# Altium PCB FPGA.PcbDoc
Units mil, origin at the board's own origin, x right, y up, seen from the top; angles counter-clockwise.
Board outline 6500 x 4500 mil, 6 copper layers (Top, VCC, GND, Route2, Route3, Bottom), stack 48.346 mil thick; 66 components, 103 nets, 452 pads, 0 vias.
Unrouted connection lines stored in the file: 258.
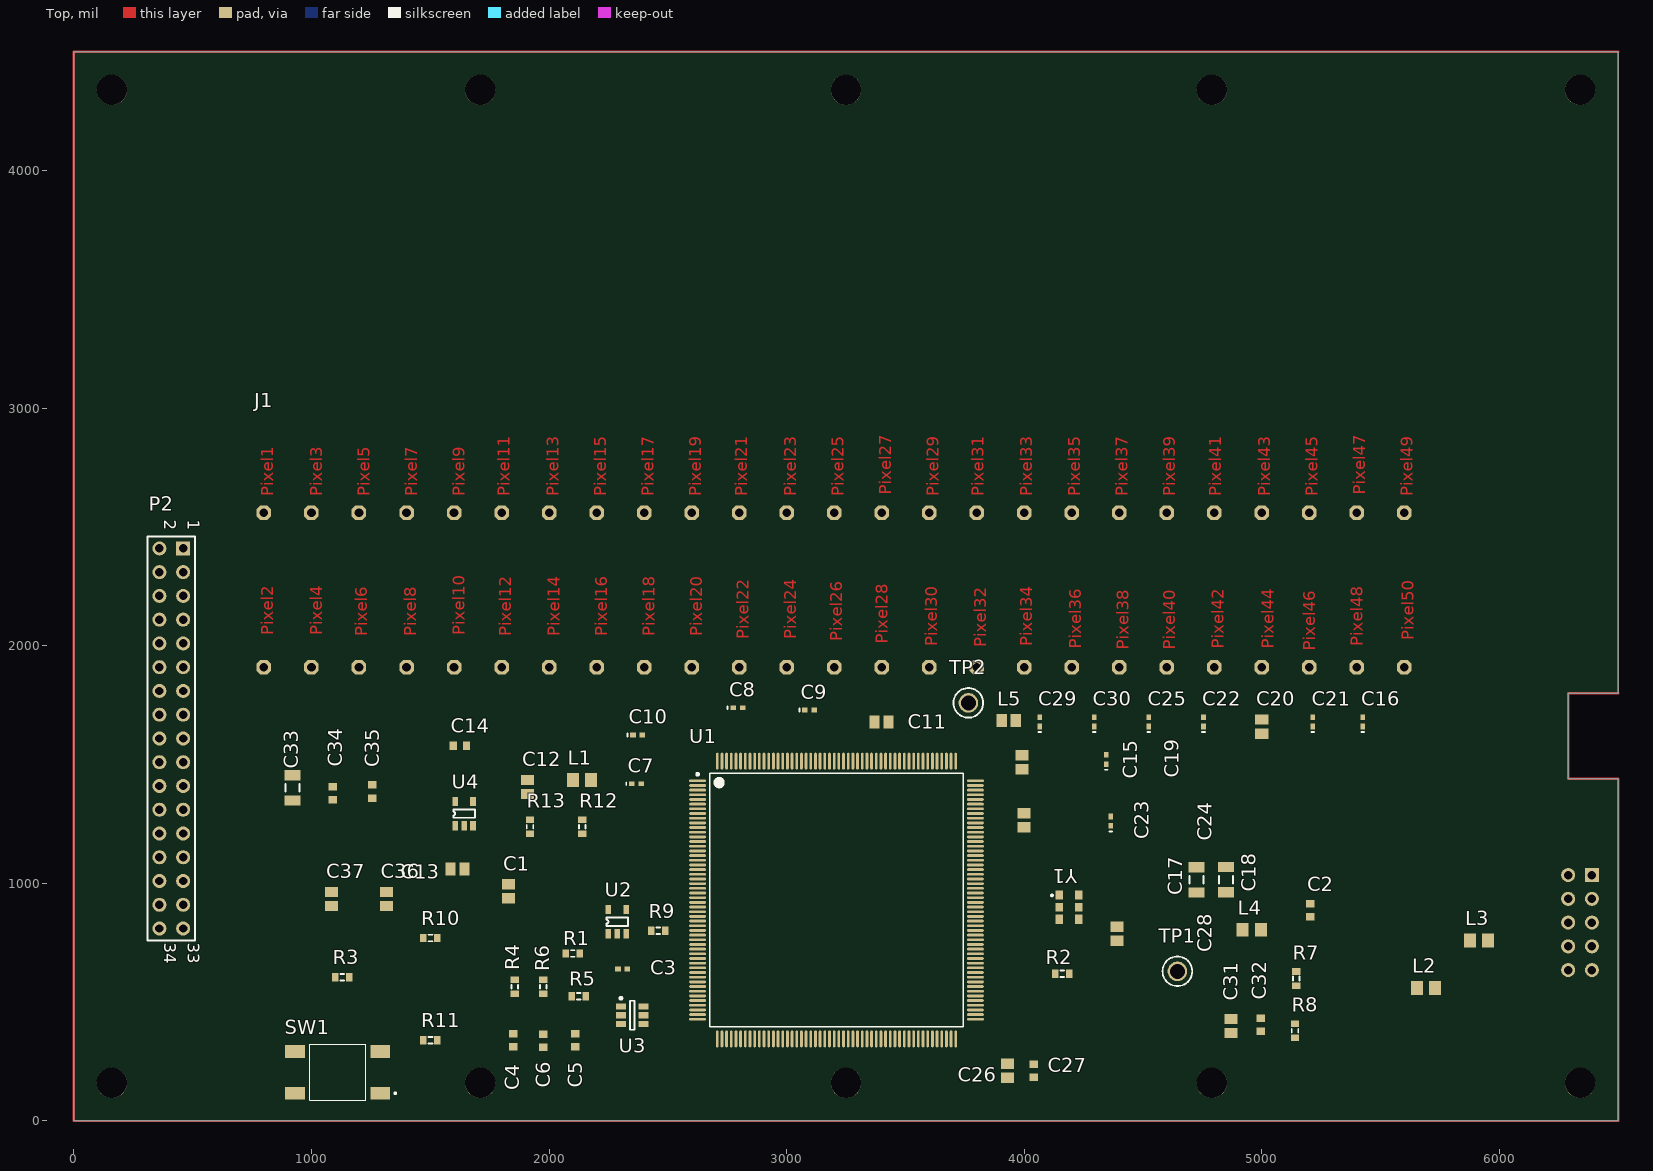
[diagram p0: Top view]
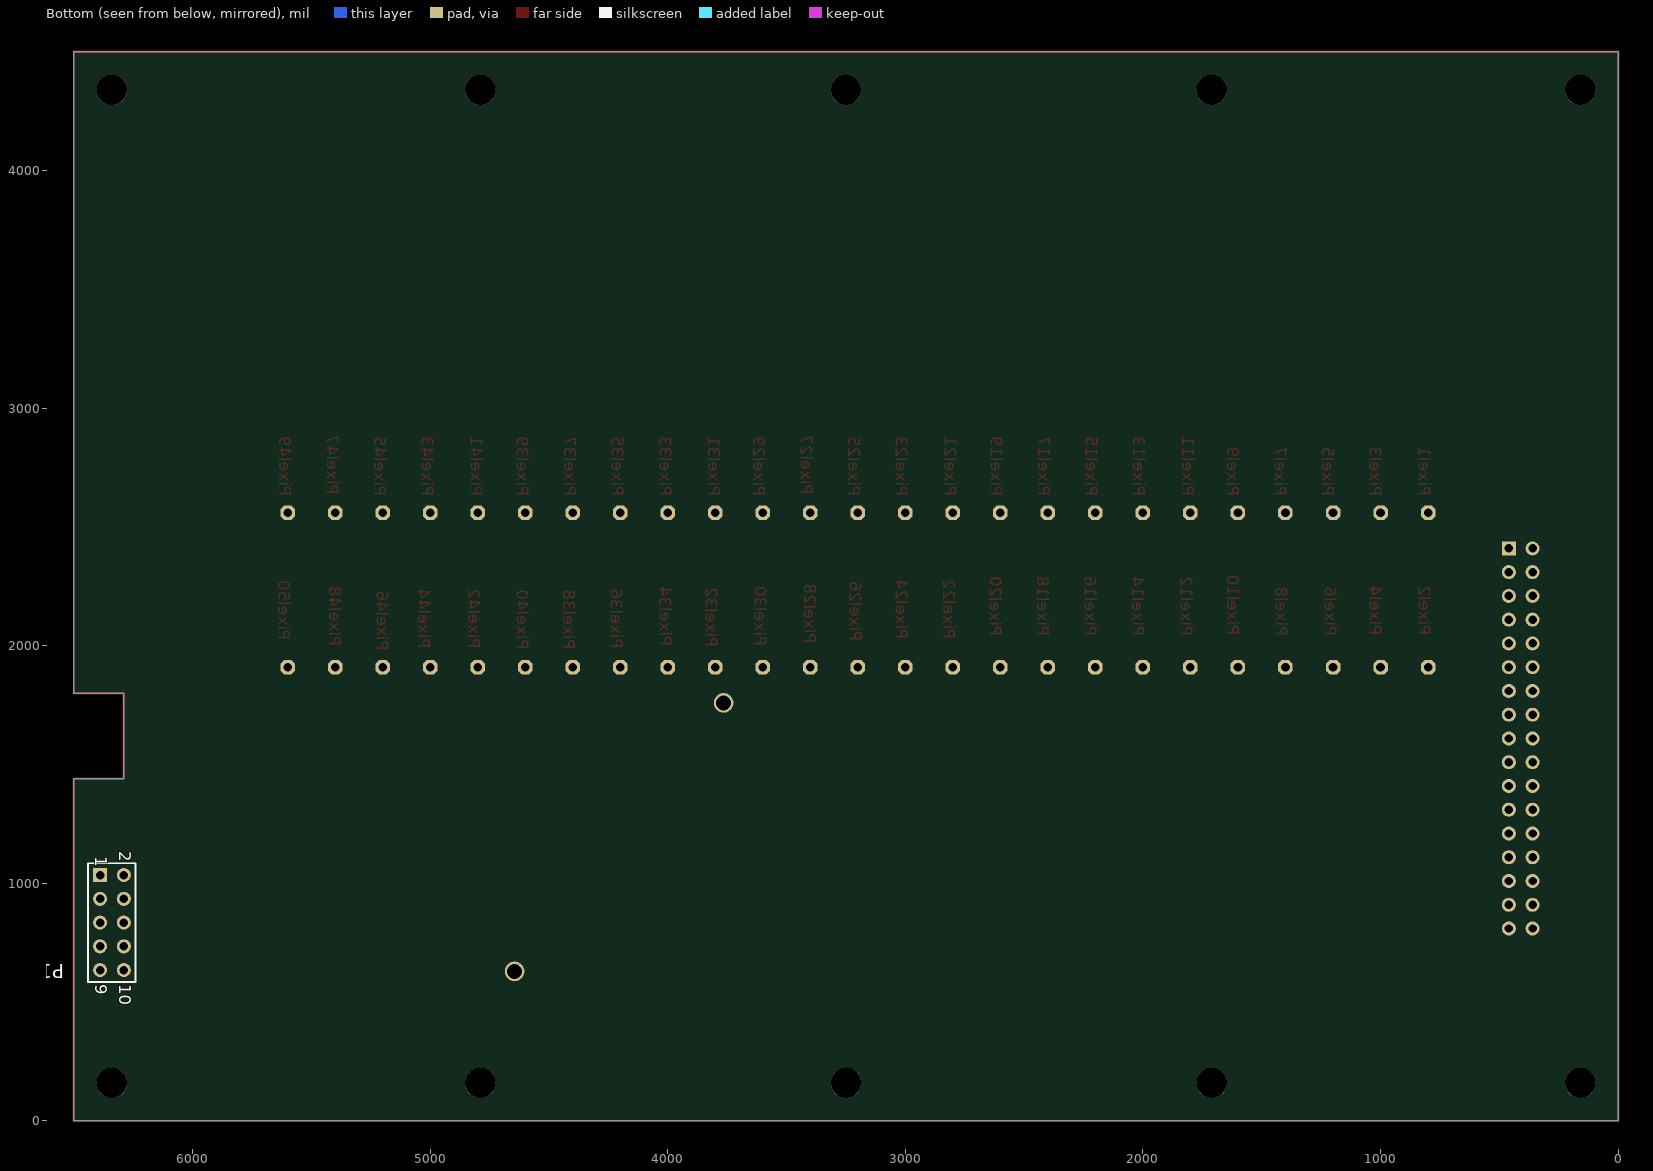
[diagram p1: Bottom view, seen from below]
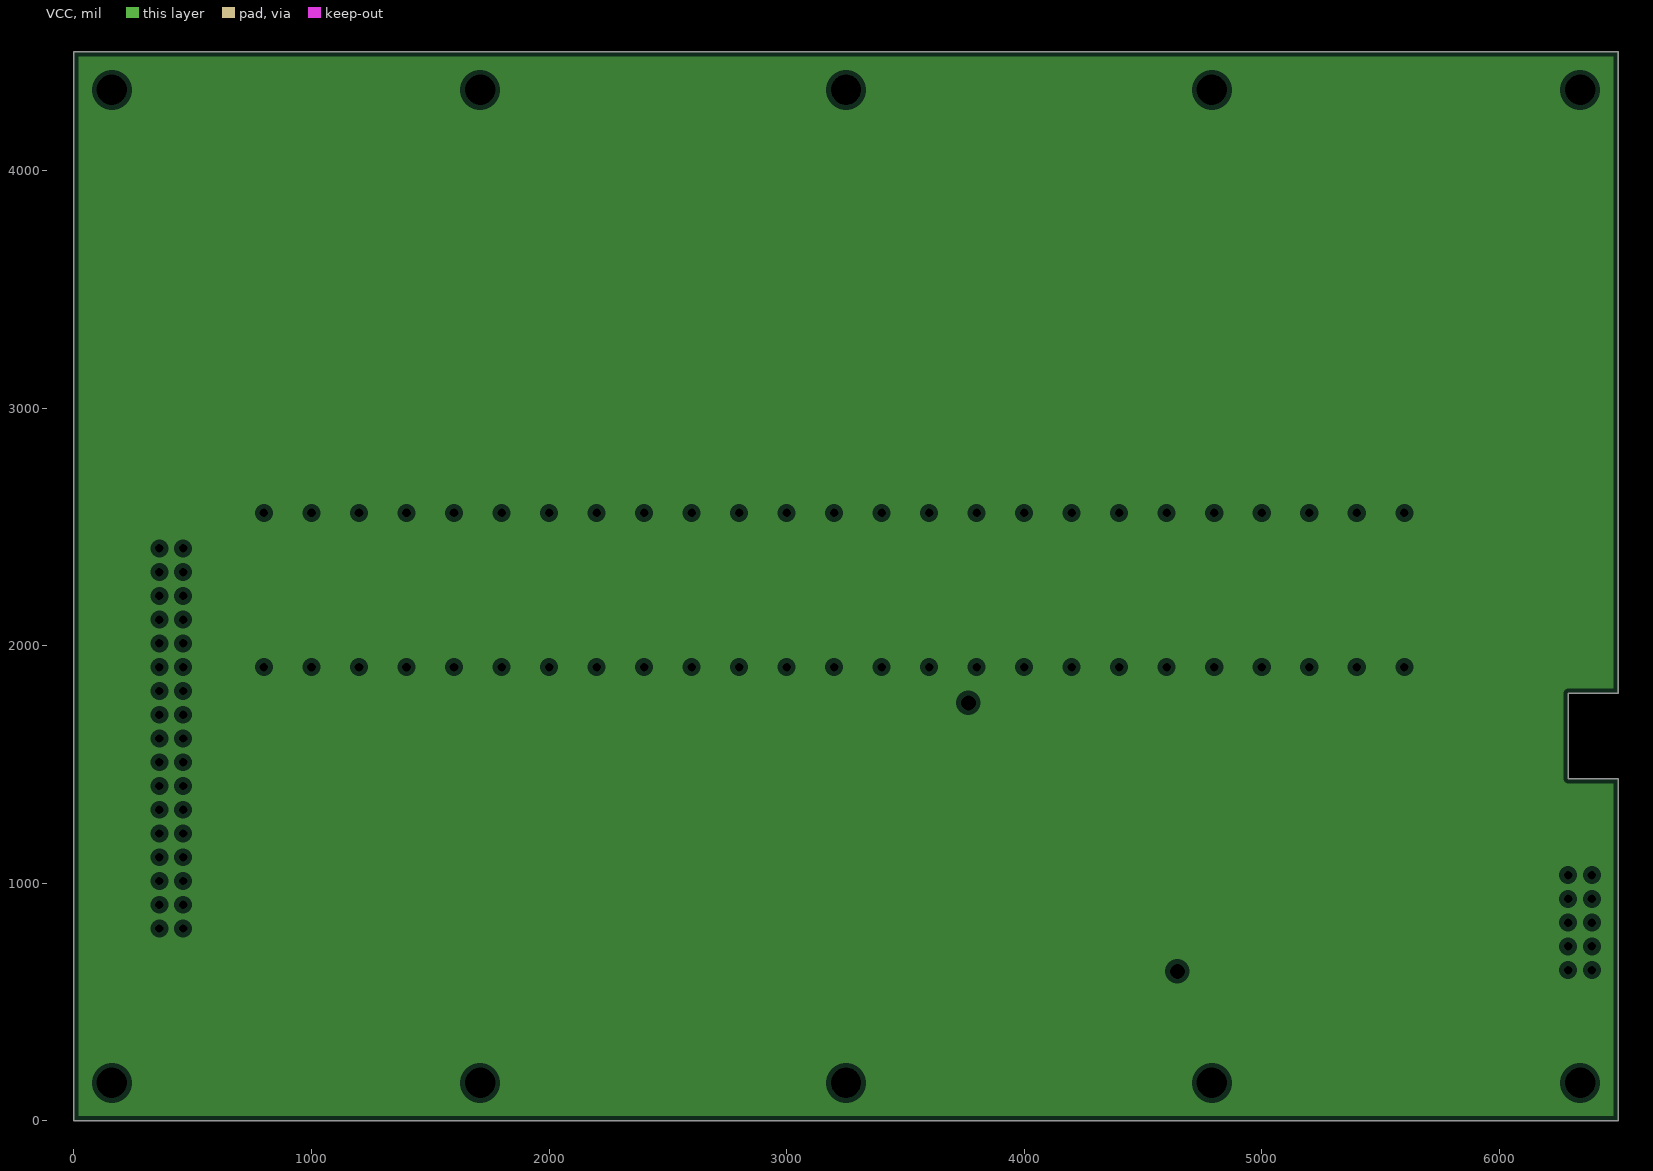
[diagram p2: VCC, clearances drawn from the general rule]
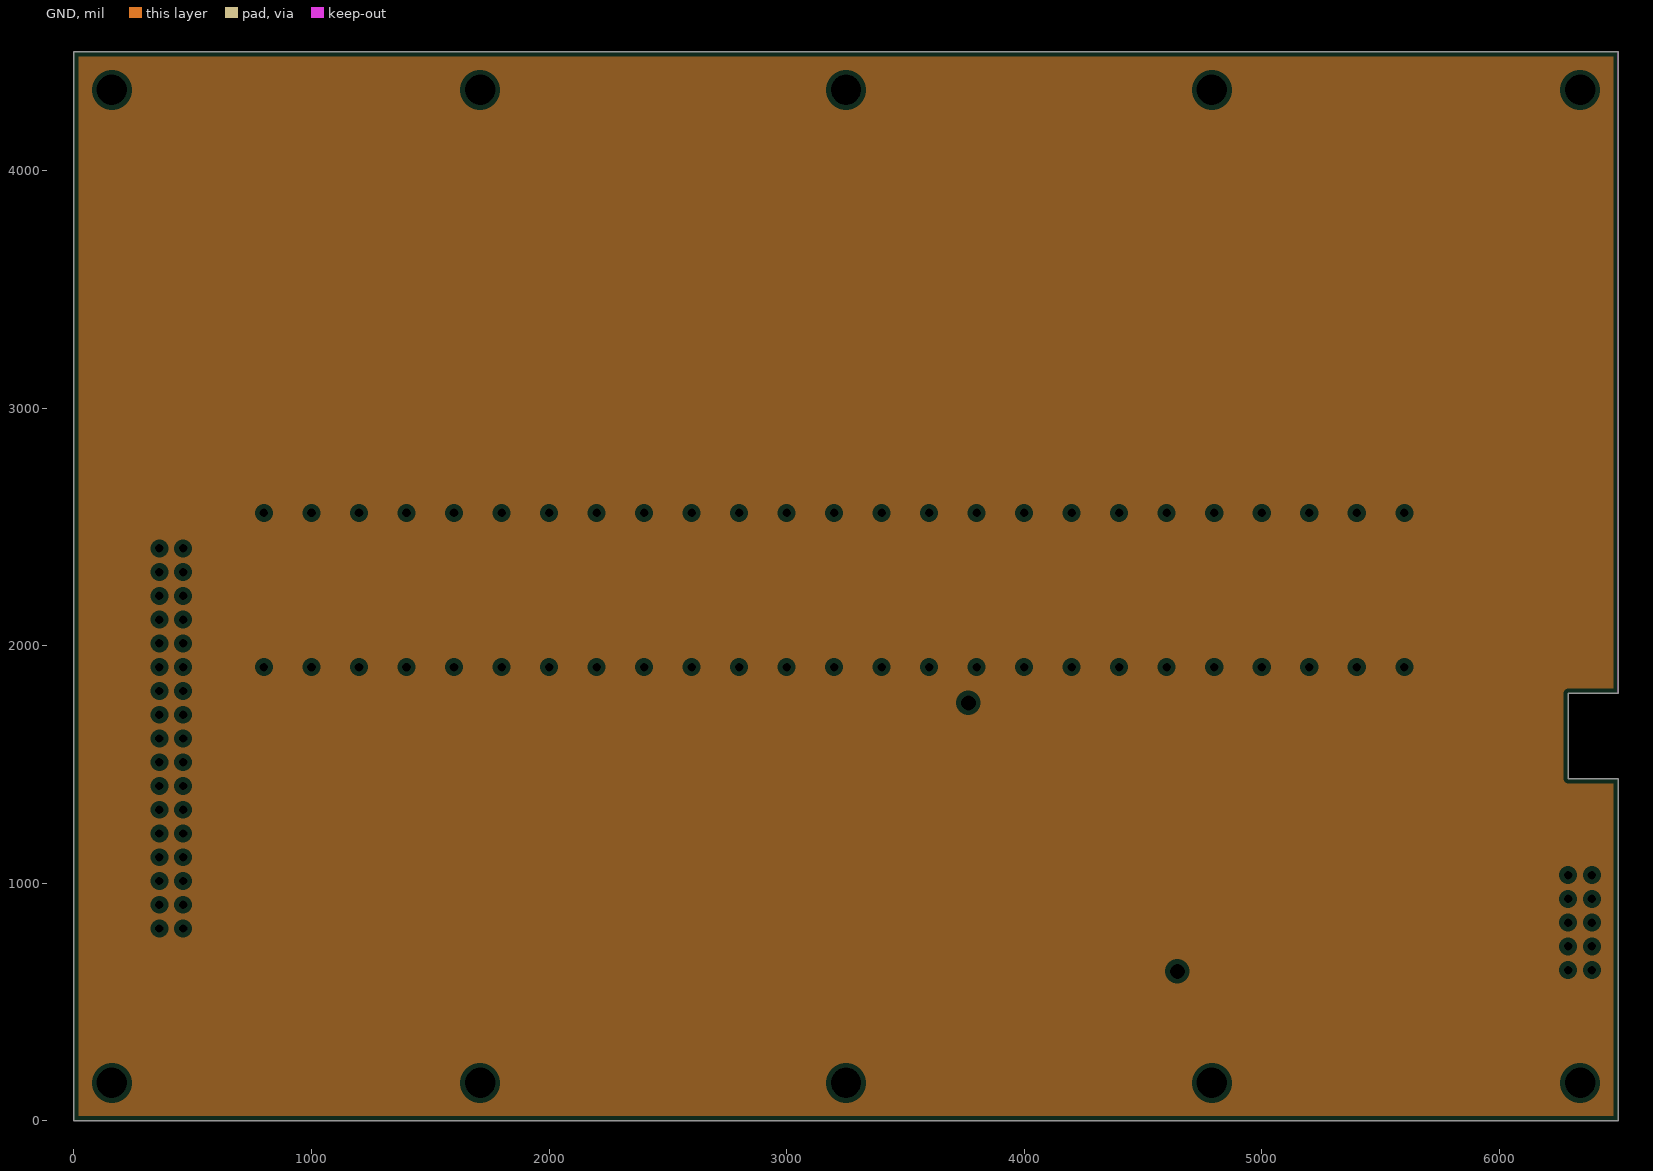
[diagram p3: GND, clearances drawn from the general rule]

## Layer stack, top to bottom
Top Solder: solder mask 0.4, Solder Resist, Dk 3.5
Top: signal copper 1.378
Dielectric 1: core 10, FR-4, Dk 4.2
VCC: plane copper 1.417
Dielectric 5: prepreg 5, Dk 4.2
GND: plane copper 1.417
Dielectric 6: core 10, Dk 4.2
Route2: signal copper 1.378
Dielectric 2: prepreg 5, FR-4, Dk 4.2
Route3: signal copper 1.378
Dielectric 4: core 10, Dk 4.2
Bottom: signal copper 1.378
Bottom Solder: solder mask 0.4, Solder Resist, Dk 3.5

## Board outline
0,0 0,4500 6500,4500 6500,1800 6290,1800 6290,1440 6500,1440 6500,0

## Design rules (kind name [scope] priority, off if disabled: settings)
Clearance [All] p1: gap=8 ignorepadtopadclearanceinfootprint=FALSE except(0: SMDPad-SMDPad SMDPad-THPad SMDPad-Via)
Clearance "Clearance (Same Net)" [All] p2: gap=0 ignorepadtopadclearanceinfootprint=FALSE except(5: Arc-Arc Arc-Track Arc-SMDPad Arc-THPad Arc-Via Arc-Fill Arc-Poly Arc-Region Arc-Hole Track-Track Track-SMDPad Track-THPad Track-Via Track-Fill Track-Poly Track-Region Track-Hole; 8: SMDPad-SMDPad SMDPad-THPad SMDPad-Via)
HoleSize HoleSize_1 [All] p1: absolutevalues=TRUE maxlimit=100000 minlimit=24 maxpercent=80.000 minpercent=20.000
HoleSize [All] p2: absolutevalues=TRUE maxlimit=100 minlimit=1 maxpercent=80.000 minpercent=20.000
HoleToHoleClearance mdViaViaSameLayer [All] p1: gap=8 allowstackedmicrovias=TRUE
HoleToHoleClearance [All] p2: gap=10 allowstackedmicrovias=TRUE
PasteMaskExpansion mlMinCreamFrame [All] p1: expansion=0
PasteMaskExpansion [All] p2: expansion=0
PlaneClearance [All] p1: clearance=20
PlaneConnect [All] p1: planeconnectstyle=Relief reliefexpansion=20 reliefentries=4 reliefconductorwidth=10 reliefairgap=10
PolygonConnect PolygonConnect_1 [All] p1: connectstyle=Relief reliefconductorwidth=10 reliefentries=4 polygonreliefangle="90 Angle" airgapwidth=10
PolygonConnect [All] p2: connectstyle=Relief reliefconductorwidth=10 reliefentries=4 polygonreliefangle="90 Angle" airgapwidth=10
RoutingVias [All] p1: holewidth=10 width=20 viastyle="Through Hole" minholewidth=20 minwidth=20 maxholewidth=28 maxwidth=50
SMDNeckDown [All] p1: percent=50.000
SilkToSilkClearance [All] p1 off: silktosilkclearance=10
SilkToSolderMaskClearance [IsPad] p1 off: minsilkscreentomaskgap=10 clearancetoexposedcopper=TRUE
SolderMaskExpansion mlMinStopFrame [All] p1: expansion=4
SolderMaskExpansion [All] p2: expansion=4
Width Width_1 [All] p1: maxlimit=100000 minlimit=5 preferedwidth=10 minimp=50.000000 maximp=50.000000 favimp=50.000000
Width [All] p2: maxlimit=10 minlimit=10 preferedwidth=10
23 further rules are at their usual default settings.

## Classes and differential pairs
component class Sheet3: J1 P2
component class Sheet2: C7 C8 C9 C10 C11 C12 C13 C14 C15 C16 C17 C18 C19 C20 C21 C22 C23 C24 C25 C26 C27 C28 C29 C30 C31 C32 C33 C34 C35 L1 L2 L3 L4 L5 P1 R7 R8 TP1 TP2 U4
component class Sheet1: C1 C2 C3 C4 C5 C6 C36 C37 R1 R2 R3 R4 R5 R6 R9 R10 R11 R12 R13 SW1 U1 U2 U3 Y1

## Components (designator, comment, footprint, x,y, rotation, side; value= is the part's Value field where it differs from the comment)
C1 "Cap Semi" C0805 1830,966.85 r270 top value=0.027uF
C2 "Cap Semi" 1608[0603] 5205,887.56 r90 top value=10nF
C3 "Cap Semi" 0402 2310,640 r180 top value=10nF
C4 "Cap Semi" 1608[0603] 1850,340 r90 top value=100pF
C5 "Cap Semi" 1608[0603] 2110,340 r90 top value=100pF
C6 "Cap Semi" 1608[0603] 1975,336.85 r90 top value=100pF
C7 "Cap Semi" 0402-A 2368.15,1420 r0 top value=0.1uF
C8 "Cap Semi" 0402-A 2795,1740 r0 top value=0.1uF
C9 "Cap Semi" 0402-A 3096.85,1730 r0 top value=0.1uF
C10 "Cap Semi" 0402-A 2373.15,1625 r0 top value=0.1uF
C11 "Cap Pol3" C0805 3399.53,1680 r180 top value=1uF
C12 "Cap Pol3" C0805 1910,1405.47 r270 top value=10uF
C13 "Cap Pol3" C0805 1614.53,1060 r0 top value="0.1uF Pol"
C14 "Cap Semi" 1608[0603] 1625,1580 r0 top value=10nF
C15 "Cap Pol3" C0805 3990,1510 r270 top value=1uF
C16 "Cap Semi" 0402-A 5425,1680 r90 top value=100nF
C17 "Cap Pol3" C1206 4725,1015 r90 top value=10uF
C18 "Cap Pol3" C1206 4850,1015.47 r90 top value=10uF
C19 "Cap Semi" 0402-A 4345,1521.85 r90 top value=10nF
C20 "Cap Pol3" C0805 5000,1660 r90 top value=1uF
C21 "Cap Semi" 0402-A 5215,1680 r90 top value=100nF
C22 "Cap Semi" 0402-A 4755,1680 r90 top value=10nF
C23 "Cap Pol3" C0805 4000,1265.47 r270 top value=1uF
C24 "Cap Semi" 0402-A 4365,1261.85 r90 top value=100nF
C25 "Cap Semi" 0402-A 4525,1680 r90 top value=10nF
C26 "Cap Pol3" C0805 3930,211.85 r270 top value=0.33uF
C27 "Cap Semi" 1608[0603] 4040,211.85 r270 top value=10nF
C28 "Cap Pol3" C0805 4390,788.15 r90 top value=1uF
C29 "Cap Semi" 0402-A 4065,1680 r90 top value=100nF
C30 "Cap Semi" 0402-A 4295,1680 r90 top value=10nF
C31 "Cap Pol3" C0805 4870,400 r90 top value=0.33uF
C32 "Cap Semi" 1608[0603] 4995,405 r90 top value=10nF
C33 "Cap Pol3" C1206 920,1401.85 r90 top value=10uF
C34 "Cap Semi" 1608[0603] 1090,1380 r270 top value=10nF
C35 "Cap Semi" 1608[0603] 1255,1386.85 r270 top value=0.1uF
C36 "Cap Pol3" C0805 1315,934.21 r90 top value="0.1uF Pol"
C37 "Cap Pol3" C0805 1085,934.21 r90 top value="0.1uF Pol"
J1 "Pixel_connector" pixel50_conn 800,1910 r0 top
L1 "MPZ2012S101A" LIRD-LI0805H151R-10-2_V 2138.29,1435 r0 top
L2 "MPZ2012S101A" LIRD-LI0805H151R-10-2_V 5691.71,560 r0 top
L3 "MPZ2012S101A" LIRD-LI0805H151R-10-2_V 5915,760 r0 top
L4 "MPZ2012S101A" LIRD-LI0805H151R-10-2_V 4958.29,805 r180 top
L5 "" C0805 3935,1685 r0 top value=6.8uH
P1 "Header 5X2" HDR2X5 6390,1035 r270 bottom
P2 "Header 17X2" HDR2X17 460,2410 r270 top
R1 "Res3" J1-0603 2100.47,705 r0 top value=20K
R2 "Res3" J1-0603 4160.47,620 r0 top value=33
R3 "Res3" J1-0603 1129.53,605 r180 top value=4.75K
R4 "Res3" J1-0603 1855,565 r270 top value=100
R5 "Res3" J1-0603 2125,525 r180 top value=100
R6 "0603" J1-0603 1975,565.47 r90 top value=100
R7 "Res3" J1-0603 5145,599.53 r90 top value=511
R8 "Res3" J1-0603 5140,379.53 r270 top value=511
R9 "Res3" J1-0603 2460,800 r0 top value=49.9
R10 "Res3" J1-0603 1500.79,770 r180 top value=100
R11 "Res3" J1-0603 1500.79,340 r180 top value=100
R12 "Res3" J1-0603 2140,1239.21 r90 top value=100
R13 "Res3" J1-0603 1920,1239.21 r90 top value=100
SW1 "FSM4JSMA" TE_FSM4JSMA 1110,205 r180 top
TP1 "5011" KSTN-5011_V 4645,630 r0 top
TP2 "5011" KSTN-5011_V 3765,1760 r0 top
U1 "A3P250L-PQ208" PQ208_N 3210,930 r0 top
U2 "SN74LVC1G17DBVR" SOT23-5 2287.4,787.64 r0 top
U3 "DAC121S101CIMK" MK06A_N 2350,445 r0 top
U4 "TPS79015DBVR" SOT23-5 1642.4,1242.64 r0 top
Y1 "OSC-50.000M" XTAL_ECX-H22BN-10.000 4188.66,900 r270 top

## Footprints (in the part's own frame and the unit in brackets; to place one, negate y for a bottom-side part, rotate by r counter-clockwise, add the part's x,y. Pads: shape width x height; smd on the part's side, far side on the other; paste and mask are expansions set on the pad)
0402 [mm] "Chip Capacitor, Body 1.0x0.5mm, IPC High Density"
  rect 0.6x0.5 smd: 1(-0.5,0) 2(0.5,0)
  body extent -0.55,-0.3 0.55,0.3, height 1.3
0402-A [mm] "Chip Inductor, Body 1.0x0.5mm, IPC High Density"
  rect 0.6x0.5 smd: 1(-0.5,0) 2(0.5,0)
  silkscreen extent -1.1,-0.15 -1.1,0.15, body extent -0.55,-0.3 0.55,0.3, height 0.55
1608[0603] [mm] "Chip Capacitor, Body 1.6x0.8mm, IPC High Density"
  rect 0.8x0.9 smd: 1(-0.7,0) 2(0.7,0)
  body extent -0.87,-0.48 0.87,0.48, height 1.3
C0805 [mm] "Chip Capacitor, Body 2.0x1.3mm, IPC High Density"
  rect 1.1x1.4 smd: 1(-0.75,0) 2(0.75,0)
  body extent -1.1,-0.72 1.1,0.72, height 1.4
C1206 [mm] "Chip Capacitor, Body 3.2x1.6mm, IPC High Density"
  rect 1.1x1.7 smd: 1(-1.35,0) 2(1.35,0)
  silkscreen extent -0.4,-0.75 0.4,0.75, body extent -1.7,-0.9 1.7,0.9, height 1.3
HDR2X5 [mm] "Connector; Header; 5x2 Position"
  rect 1.5x1.5 hole 0.9: 1(0,0)
  round 1.5 hole 0.9: 2(0,2.54) 3(2.54,0) 4(2.54,2.54) 5(5.08,0) 6(5.08,2.54) 7(7.62,0) 8(7.62,2.54) 9(10.16,0) 10(10.16,2.54)
  silkscreen extent -1.27,-1.27 11.43,3.81
HDR2X17 [mm] "Connector; Header; 17x2 Position"
  rect 1.5x1.5 hole 0.9: 1(0,0)
  round 1.5 hole 0.9: 2(0,-2.54) 3(2.54,0) 4(2.54,-2.54) 5(5.08,0) 6(5.08,-2.54) 7(7.62,0) 8(7.62,-2.54) 9(10.16,0) 10(10.16,-2.54) 11(12.7,0) 12(12.7,-2.54) 13(15.24,0) 14(15.24,-2.54) 15(17.78,0) 16(17.78,-2.54) 17(20.32,0) 18(20.32,-2.54) 19(22.86,0) 20(22.86,-2.54) 21(25.4,0) 22(25.4,-2.54) 23(27.94,0) 24(27.94,-2.54) 25(30.48,0) 26(30.48,-2.54) 27(33.02,0) 28(33.02,-2.54) 29(35.56,0) 30(35.56,-2.54) 31(38.1,0) 32(38.1,-2.54) 33(40.64,0) 34(40.64,-2.54)
  silkscreen extent -1.27,-3.81 41.91,1.27
J1-0603 [mm] "Chip Resistor, Body 1.6x0.8mm, IPC High Density"
  rect 0.7x0.9 smd: 1(-0.75,0) 2(0.75,0)
  silkscreen extent -0.2,-0.35 0.2,0.35, body extent -0.85,-0.48 0.85,0.48, height 0.9
KSTN-5011_V [mm] "Test Point, Dia 3.17mm"
  round 2.1 hole 1.6: 1(0,0)
  silkscreen extent -1.59,-1.58 1.59,1.58, body extent -1.59,-1.59 1.59,1.59, height 8.13
LIRD-LI0805H151R-10-2_V [mm] "Chip, 2-Leads, Body 2.2x1.45mm"
  rect 1.285x1.47 smd: 1(-0.972,0) 2(0.972,0)
  body extent -1.1,-0.72 1.1,0.73, height 1.1
MK06A_N [mm] "SOT23, 6-Leads, Body 3.0x1.7mm, Pitch 0.95mm, Lead Span 2.9mm, IPC Medium Density"
  rect 1.1x0.65 smd: 1(-1.2,0.95) 2(-1.2,0) 3(-1.2,-0.95) 4(1.2,-0.95) 5(1.2,0) 6(1.2,0.95)
  silkscreen extent -1.32,-1.55 0.25,1.95, body extent -0.87,-1.53 0.87,1.54, height 1
pixel50_conn [mil] "Pixel Connector 50"
  oct 61x61 hole 36: 1(0,650) 2(0,0) 3(200,650) 4(200,0) 5(400,650) 6(400,0) 7(600,650) 8(600,0) 9(800,650) 10(800,0) 11(1000,650) 12(1000,0) 13(1200,650) 14(1200,0) 15(1400,650) 16(1400,0) 17(1600,650) 18(1600,0) 19(1800,650) 20(1800,0) 21(2000,650) 22(2000,0) 23(2200,650) 24(2200,0) 25(2400,650) 26(2400,0) 27(2600,650) 28(2600,0) 29(2800,650) 30(2800,0) 31(3000,650) 32(3000,0) 33(3200,650) 34(3200,0) 35(3400,650) 36(3400,0) 37(3600,650) 38(3600,0) 39(3800,650) 40(3800,0) 41(4000,650) 42(4000,0) 43(4200,650) 44(4200,0) 45(4400,650) 46(4400,0) 47(4600,650) 48(4600,0) 49(4800,650) 50(4800,0)
PQ208_N [mm] "Shrink QFP, 208-Leads, Body 28x28mm, Pitch 0.5mm, IPC Medium Density"
  oval 1.8x0.3 smd: 1(-14.85,12.75) 2(-14.85,12.25) 3(-14.85,11.75) 4(-14.85,11.25) 5(-14.85,10.75) 6(-14.85,10.25) 7(-14.85,9.75) 8(-14.85,9.25) 9(-14.85,8.75) 10(-14.85,8.25) 11(-14.85,7.75) 12(-14.85,7.25) 13(-14.85,6.75) 14(-14.85,6.25) 15(-14.85,5.75) 16(-14.85,5.25) 17(-14.85,4.75) 18(-14.85,4.25) 19(-14.85,3.75) 20(-14.85,3.25) 21(-14.85,2.75) 22(-14.85,2.25) 23(-14.85,1.75) 24(-14.85,1.25) 25(-14.85,0.75) 26(-14.85,0.25) 27(-14.85,-0.25) 28(-14.85,-0.75) 29(-14.85,-1.25) 30(-14.85,-1.75) 31(-14.85,-2.25) 32(-14.85,-2.75) 33(-14.85,-3.25) 34(-14.85,-3.75) 35(-14.85,-4.25) 36(-14.85,-4.75) 37(-14.85,-5.25) 38(-14.85,-5.75) 39(-14.85,-6.25) 40(-14.85,-6.75) 41(-14.85,-7.25) 42(-14.85,-7.75) 43(-14.85,-8.25) 44(-14.85,-8.75) 45(-14.85,-9.25) 46(-14.85,-9.75) 47(-14.85,-10.25) 48(-14.85,-10.75) 49(-14.85,-11.25) 50(-14.85,-11.75) 51(-14.85,-12.25) 52(-14.85,-12.75) 105(14.85,-12.75) 106(14.85,-12.25) 107(14.85,-11.75) 108(14.85,-11.25) 109(14.85,-10.75) 110(14.85,-10.25) 111(14.85,-9.75) 112(14.85,-9.25) 113(14.85,-8.75) 114(14.85,-8.25) 115(14.85,-7.75) 116(14.85,-7.25) 117(14.85,-6.75) 118(14.85,-6.25) 119(14.85,-5.75) 120(14.85,-5.25) 121(14.85,-4.75) 122(14.85,-4.25) 123(14.85,-3.75) 124(14.85,-3.25) 125(14.85,-2.75) 126(14.85,-2.25) 127(14.85,-1.75) 128(14.85,-1.25) 129(14.85,-0.75) 130(14.85,-0.25) 131(14.85,0.25) 132(14.85,0.75) 133(14.85,1.25) 134(14.85,1.75) 135(14.85,2.25) 136(14.85,2.75) 137(14.85,3.25) 138(14.85,3.75) 139(14.85,4.25) 140(14.85,4.75) 141(14.85,5.25) 142(14.85,5.75) 143(14.85,6.25) 144(14.85,6.75) 145(14.85,7.25) 146(14.85,7.75) 147(14.85,8.25) 148(14.85,8.75) 149(14.85,9.25) 150(14.85,9.75) 151(14.85,10.25) 152(14.85,10.75) 153(14.85,11.25) 154(14.85,11.75) 155(14.85,12.25) 156(14.85,12.75)
  oval 0.3x1.8 smd: 53(-12.75,-14.85) 54(-12.25,-14.85) 55(-11.75,-14.85) 56(-11.25,-14.85) 57(-10.75,-14.85) 58(-10.25,-14.85) 59(-9.75,-14.85) 60(-9.25,-14.85) 61(-8.75,-14.85) 62(-8.25,-14.85) 63(-7.75,-14.85) 64(-7.25,-14.85) 65(-6.75,-14.85) 66(-6.25,-14.85) 67(-5.75,-14.85) 68(-5.25,-14.85) 69(-4.75,-14.85) 70(-4.25,-14.85) 71(-3.75,-14.85) 72(-3.25,-14.85) 73(-2.75,-14.85) 74(-2.25,-14.85) 75(-1.75,-14.85) 76(-1.25,-14.85) 77(-0.75,-14.85) 78(-0.25,-14.85) 79(0.25,-14.85) 80(0.75,-14.85) 81(1.25,-14.85) 82(1.75,-14.85) 83(2.25,-14.85) 84(2.75,-14.85) 85(3.25,-14.85) 86(3.75,-14.85) 87(4.25,-14.85) 88(4.75,-14.85) 89(5.25,-14.85) 90(5.75,-14.85) 91(6.25,-14.85) 92(6.75,-14.85) 93(7.25,-14.85) 94(7.75,-14.85) 95(8.25,-14.85) 96(8.75,-14.85) 97(9.25,-14.85) 98(9.75,-14.85) 99(10.25,-14.85) 100(10.75,-14.85) 101(11.25,-14.85) 102(11.75,-14.85) 103(12.25,-14.85) 104(12.75,-14.85) 157(12.75,14.85) 158(12.25,14.85) 159(11.75,14.85) 160(11.25,14.85) 161(10.75,14.85) 162(10.25,14.85) 163(9.75,14.85) 164(9.25,14.85) 165(8.75,14.85) 166(8.25,14.85) 167(7.75,14.85) 168(7.25,14.85) 169(6.75,14.85) 170(6.25,14.85) 171(5.75,14.85) 172(5.25,14.85) 173(4.75,14.85) 174(4.25,14.85) 175(3.75,14.85) 176(3.25,14.85) 177(2.75,14.85) 178(2.25,14.85) 179(1.75,14.85) 180(1.25,14.85) 181(0.75,14.85) 182(0.25,14.85) 183(-0.25,14.85) 184(-0.75,14.85) 185(-1.25,14.85) 186(-1.75,14.85) 187(-2.25,14.85) 188(-2.75,14.85) 189(-3.25,14.85) 190(-3.75,14.85) 191(-4.25,14.85) 192(-4.75,14.85) 193(-5.25,14.85) 194(-5.75,14.85) 195(-6.25,14.85) 196(-6.75,14.85) 197(-7.25,14.85) 198(-7.75,14.85) 199(-8.25,14.85) 200(-8.75,14.85) 201(-9.25,14.85) 202(-9.75,14.85) 203(-10.25,14.85) 204(-10.75,14.85) 205(-11.25,14.85) 206(-11.75,14.85) 207(-12.25,14.85) 208(-12.75,14.85)
  silkscreen extent -14.97,-13.55 13.55,13.57, body extent -14,-14 14,14, height 4.1
SOT23-5 [mm] "SOT143-4 as used in SP0503BAHTG"
  round 0.2 on Top Overlay: 1(-1.5,0.75)
  rect 0.6x1 smd: 1(-0.95,0) 2(0,0) 3(0.95,0) 4(0.95,2.6) 5(-0.95,2.6)
  silkscreen extent -1.15,0.85 1.15,1.75, body extent -1.46,0.13 1.46,2.47, height 1
TE_FSM4JSMA [mm]
  rect 2.1x1.38 smd: 1(-4.55,2.24) 2(4.55,2.24) 3(-4.55,-2.24) 4(4.55,-2.24)
  silkscreen extent -6.25,-3 3,3
XTAL_ECX-H22BN-10.000 [mm]
  rect 1x0.8 smd: 1(-1.3,-1.05) 3(1.3,-1.05) 4(1.3,1.05) 6(-1.3,1.05)
  rect 0.9x0.8 smd: 2(0,-1.05) 5(0,1.05)
  silkscreen extent -1.35,-1.92 -1.15,-1.72

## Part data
C1: "0.027uF", Supplier Part Number 1=399-1164-1-ND
C2 C14 C27 C32 C34: "10nF", Supplier Part Number 1=399-3189-1-ND
C3: "10nF", Supplier Part Number 1=399-3066-1-ND
C4 C5 C6: "100pF", Supplier Part Number 1=399-7818-1-ND
C7 C8 C9 C35: "0.1uF", Supplier Part Number 1=445-15958-1-ND
C10: "0.1uF", Supplier Part Number 1=399-8942-1-ND
C11: "1uF Pol", Supplier Part Number 1=478-3962-1-ND
C12: "10uF Pol", Supplier Part Number 1=478-1655-1-ND
C13 C36 C37: "0.1uF pol", Supplier Part Number 1=399-8263-1-ND
C15 C20 C23 C28: "1uF", Supplier Part Number 1=718-1121-1-ND
C16 C21 C24 C29: "100nF", Supplier Part Number 1=720-1532-1-ND
C17 C18: "10uF Pol", Supplier Part Number 1=478-8235-1-ND
C19 C22 C25 C30: "10nF", Supplier Part Number 1=720-1376-1-ND
C26 C31: "0.33uF Pol", Supplier Part Number 1=478-11071-1-ND
C33: "10 uF", Supplier Part Number 1=478-8235-1-ND
J1: "CustomPins"
L1 L2 L3 L4: library part CMP-2000-06404-1, "FB, 100ohm", Current Rating (Max)=5A, DC Resistance (DCR) (Max)=10mOhm, Impedance @ Frequency=80Ohm@100MHz, Manufacturer=Laird, Operating Temperature=-40癈~125癈, Package / Case=0805(2012Metric), Package Description="2-Pin Surface Mount Device, Body 2 x 1.25 mm", Package Reference=LI0805H15R-10-2, Package Version="Rev. D, 08/2013", Ratings=-, Standard Package=1, Supplier Part Number 1=445-1567-1-ND
L5: library part Inductor, "Inductor", Supplier Part Number 1=445-1057-1-ND
P1: "Header, 5-Pin, Dual row", Supplier Part Number 1=WM4634-ND
P2: "Header, 17-Pin, Dual row", Supplier Part Number 1=92P0473
R1: "20K", Supplier Part Number 1=541-20.0KTCT-ND
R2: "33ohm", Supplier Part Number 1=P33.0HCT-ND
R3: "4.75K", Supplier Part Number 1=541-47.5KTCT-ND
R4 R5 R10 R11 R12 R13: "100ohm", Supplier Part Number 1=P100HCT-ND
R6: library part Res3, "100ohm", Supplier Part Number 1=P100HCT-ND
R7 R8: "511ohm", Supplier Part Number 1=541-3008-1-ND
R9: "49.9", Supplier Part Number 1=RMCF0402FT49R9CT-ND
SW1: "PB SW", Package=None, Supplier Part Number 1=450-1129-ND
TP1 TP2: library part CMP-1672-00003-4, "Test Point, Black, Through Hole, RoHS, Bulk", Colour=Black, Manufacturer=Keystone, Package Quantity=100, Supplier Part Number 1=36-5011-ND
U1: "ProASIC3L Low-Power Flash Family FPGA, 151 User IOs, 250K System Gates, 36 Kbits RAM, 1 Kbit FlashROM, 1PLL, 208-Pin PQFP, Commercial Grade", Supplier Part Number 1=1100-1028-ND
U2: "Single Schmitt-Trigger Buffer, DBV0005A, LARGE T&R", F @ Nom Voltage(Max)(Mhz)=150, Generic Part Number=SN74LVC1G17, ICC @ Nom Voltage(Max)(mA)=0.01, Manufacturer="Texas Instruments", Operating Temperature Range(C)="-40 to 125,-40 to 85", Rating=Catalog, Supplier Part Number 1=595-SN74LVC1G17DBVR, tpd @ Nom Voltage(Max)(ns)=11,6.5,5.5,5, Voltage(Nom)(V)=1.8,2.5,3.3,5
U3: "12-Bit Micro Power Digital-to-Analog Converter with Rail-to-Rail Output, 6-pin Tiny SOT23", Manufacturer="National Semiconductor", PackageTopMarking=X61C*XTT, PowerWise=Y, Supplier Part Number 1=296-38083-1-ND
U4: "Single Output Low Noise LDO, 50 mA, Fixed 1.5 V Output, 2.7 to 10 V Input, with Low IQ, 5-pin SOT-23 (DBV), -40 to 125 degC, Green (RoHS & no Sb/Br)", Manufacturer="Texas Instruments", Rating=Catalog, Supplier Part Number 1=296-8151-2-ND
Y1: library part ECX-H22CM-50.000, "OSC XO 50.0000MHZ HCMOS SMD", Package="SMD-6 ECS International", Supplier Part Number 1=CTX1011CT-ND

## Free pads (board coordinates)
  round 128 hole 128: 1(160,160) 1(160,4340) 1(1710,160) 1(1710,4340) 1(3250,160) 1(3250,4340) 1(4790,160) 1(4790,4340) 1(6340,160) 1(6340,4340)

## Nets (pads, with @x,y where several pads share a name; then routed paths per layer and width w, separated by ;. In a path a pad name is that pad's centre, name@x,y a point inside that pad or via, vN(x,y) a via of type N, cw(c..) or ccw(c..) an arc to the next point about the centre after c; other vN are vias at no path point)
3.3VD: L2.1 L3.1
+1.5VD: C12.1 L1.1 L5.1 TP2.1 U4.5
+3.3VD: C2.2 C3.2 C13.1 C36.1 C37.1 L4.1 P2.1 SW1.3 SW1.4 TP1.1 U2.5 U3.3 U4.1@1605,1242.64 Y1.6
ADC_CLK: P2.28 U1.8
ADC_CS1: P2.25 U1.10
ADC_CS2: P2.23 U1.11
ADC_SDI: P2.30 U1.9
ADC_SDO: P2.26 U1.12
CNT_DATA: P2.32 U1.23
CNT_GTCLK: P2.33 U1.33
CNT_INVLOAD: P2.31 U1.24
DAC1_SCLK: R5.2 U1.47 U3.5
DAC1_SDI: R4.2 U1.48 U3.4
DAC1_SYNCn: R6.2 U1.49 U3.6
GND: C1.1 C2.1 C3.1 C4.1 C5.1 C6.1 C7.1 C8.1 C9.1 C10.1 C11.2 C12.2 C13.2 C14.1 C15.2 C16.1 C17.2 C18.2 C19.1 C20.2 C21.1 C22.1 C23.2 C24.1 C25.1 C26.2 C27.1 C28.2 C29.1 C30.1 C31.2 C32.1 C33.2 C34.1 C35.1 C36.2 C37.2 P1.2 P1.10 P2.2 P2.16 P2.17 P2.18 P2.24 R3.2 R7.1 R8.1 U1.1 U1.17 U1.25 U1.29 U1.41 U1.51 U1.52 U1.65 U1.81 U1.97 U1.100 U1.105 U1.122 U1.130 U1.141 U1.155 U1.156 U1.162 U1.178 U1.195 U1.207 U2.3 U3.2 U4.2 U4.3 Y1.3
HK_DATA: P2.34 U1.19
HK_GTCLK: P2.29 U1.22
HK_INVLOAD: P2.27 U1.20
HVEN: P2.10 R9.1
HVEN_CMD_N: P2.21 R10.1
MCP_DAC_CLK: P2.13 U1.15
MCP_DAC_CS: P2.11 U1.14
MCP_DAC_SDI: P2.15 U1.13
NetC1_2: C1.2 R1.2 U2.2
NetC4_2: C4.2 R4.1
NetC5_2: C5.2 R5.1
NetC6_2: C6.2 R6.1
NetC14_2: C14.2 U4.4
NetC33_1: C33.1 C34.2 C35.2 L5.2 U1.27
NetP1_1: P1.1 R7.2 U1.101
NetP1_3: P1.3 U1.108
NetP1_5: P1.5 U1.103
NetP1_8: P1.8 R8.2 U1.109
NetP1_9: P1.9 U1.102
NetR1_1: R1.1 SW1.1
NetR2_2: R2.2 Y1.4
NetR3_1: R3.1 SW1.2
NetR9_2: R9.2 U1.39
NetR10_2: R10.2 U1.32
NetR11_2: R11.2 U1.30
NetR12_2: R12.2 U1.26
NetR13_2: R13.2 U1.28
NetU1_55: U1.55 U2.4
pixel1: J1.1 U1.2
pixel2: J1.2 U1.3
pixel3: J1.3 U1.4
pixel4: J1.4 U1.5
pixel5: J1.5 U1.6
pixel6: J1.6 U1.7
pixel7: J1.7 U1.205
pixel8: J1.8 U1.204
pixel9: J1.9 U1.203
pixel10: J1.10 U1.202
pixel11: J1.11 U1.201
pixel12: J1.12 U1.199
pixel13: J1.13 U1.198
pixel14: J1.14 U1.197
pixel15: J1.15 U1.196
pixel16: J1.16 U1.194
pixel17: J1.17 U1.193
pixel18: J1.18 U1.192
pixel19: J1.19 U1.191
pixel20: J1.20 U1.190
pixel21: J1.21 U1.189
pixel22: J1.22 U1.188
pixel23: J1.23 U1.185
pixel24: J1.24 U1.184
pixel25: J1.25 U1.183
pixel26: J1.26 U1.181
pixel27: J1.27 U1.180
pixel28: J1.28 U1.179
pixel29: J1.29 U1.177
pixel30: J1.30 U1.176
pixel31: J1.31 U1.175
pixel32: J1.32 U1.174
pixel33: J1.33 U1.173
pixel34: J1.34 U1.172
pixel35: J1.35 U1.169
pixel36: J1.36 U1.168
pixel37: J1.37 U1.167
pixel38: J1.38 U1.166
pixel39: J1.39 U1.165
pixel40: J1.40 U1.164
pixel41: J1.41 U1.163
pixel42: J1.42 U1.161
pixel43: J1.43 U1.160
pixel44: J1.44 U1.159
pixel45: J1.45 U1.158
pixel46: J1.46 U1.153
pixel47: J1.47 U1.152
pixel48: J1.48 U1.151
pixel49: J1.49 U1.150
pixel50: J1.50 U1.149
RESET_CMD_N: P2.22 R12.1
SAFE_CMD: P2.20 R11.1
STIM_CMD_N: P2.19 R13.1
SYNC: P2.14 U1.31
SYSCLK: R2.1 U1.98
THRESH: P2.7 U3.1
VBANK: C15.1 C16.2 C17.1 C18.1 C19.2 C20.1 C21.2 C22.2 C23.1 C24.2 C25.2 C28.1 C29.2 C30.2 L4.2 U1.18 U1.40 U1.50 U1.62 U1.72 U1.89 U1.104 U1.123 U1.140 U1.154 U1.170 U1.186 U1.200 U1.208
VCORE: C7.2 C8.2 C9.2 C10.2 C11.1 L1.2 U1.16 U1.71 U1.88 U1.126 U1.142 U1.171 U1.187
VJTAG: C26.1 C27.2 L3.2 P1.6 U1.110
VPUMP: C31.1 C32.2 L2.2 P1.7 U1.106
pads on no net: P1.4 P2.3 P2.4 P2.5 P2.6 P2.8 P2.9 P2.12 U1.21 U1.34 U1.35 U1.36 U1.37 U1.38 U1.42 U1.43 U1.44 U1.45 U1.46 U1.53 U1.54 U1.56 U1.57 U1.58 U1.59 U1.60 U1.61 U1.63 U1.64 U1.66 U1.67 U1.68 U1.69 U1.70 U1.73 U1.74 U1.75 U1.76 U1.77 U1.78 U1.79 U1.80 U1.82 U1.83 U1.84 U1.85 U1.86 U1.87 U1.90 U1.91 U1.92 U1.93 U1.94 U1.95 U1.96 U1.99 U1.107 U1.111 U1.112 U1.113 U1.114 U1.115 U1.116 U1.117 U1.118 U1.119 U1.120 U1.121 U1.124 U1.125 U1.127 U1.128 U1.129 U1.131 U1.132 U1.133 U1.134 U1.135 U1.136 U1.137 U1.138 U1.139 U1.143 U1.144 U1.145 U1.146 U1.147 U1.148 U1.157 U1.182 U1.206 U2.1 U4.1@1583.35,1272.17 Y1.1 Y1.2 Y1.5
copper on no net: | length 19720
  Top w10: 6500,1800 6290,1800 6290,1440 6500,1440 6500,0 0,0 0,4500 6500,4500

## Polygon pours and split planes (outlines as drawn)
no net on VCC (split plane): 6479.9,1820.1 6290,1820.1 6286.08,1819.71 6282.31,1818.57 6278.83,1816.71 6275.79,1814.21 6273.29,1811.17 6271.43,1807.69 6270.29,1803.92 6269.9,1800 6269.9,1440 6270.29,1436.08 6271.43,1432.31 6273.29,1428.83 6275.79,1425.79 6278.83,1423.29 6282.31,1421.43 6286.08,1420.29 6290,1419.9 6479.9,1419.9 6479.9,20.1 20.1,20.1 20.1,4479.9 6479.9,4479.9
no net on GND (split plane): 6479.9,1820.1 6290,1820.1 6286.08,1819.71 6282.31,1818.57 6278.83,1816.71 6275.79,1814.21 6273.29,1811.17 6271.43,1807.69 6270.29,1803.92 6269.9,1800 6269.9,1440 6270.29,1436.08 6271.43,1432.31 6273.29,1428.83 6275.79,1425.79 6278.83,1423.29 6282.31,1421.43 6286.08,1420.29 6290,1419.9 6479.9,1419.9 6479.9,20.1 20.1,20.1 20.1,4479.9 6479.9,4479.9

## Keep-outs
Keep-Out Layer:
  lines w0: 6500,1800 6500,4500

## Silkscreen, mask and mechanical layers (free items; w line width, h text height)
Dimension:
  lines w10: -360,-45 -340,15 ; -360,235 -340,175 ; -350,15 -330,15 ; -350,175 -330,175 ; -340,-85 -340,15 ; -340,275 -340,175 ; -320,-45 -340,15 ; -320,235 -340,175 ; -150,60 -130,0 ; -150,4440 -130,4500 ; -140,0 -120,0 ; -140,4500 -120,4500 ; -130,1969.09 -130,0 ; -130,2530.91 -130,4500 ; -110,60 -130,0 ; -110,4440 -130,4500 ; -105,80 -5,80 ; -65,60 -5,80 ; -65,100 -5,80 ; -5,70 -5,90 ; 0,-410 0,-390 ; 0,-330 0,-310 ; 0,-265 0,-245 ; 0,-205 0,-185 ; 0,-110 0,-90 ; 0,2660 0,2680 ; 0,3185 0,3205 ; 60,-420 0,-400 ; 60,-380 0,-400 ; 60,-340 0,-320 ; 60,-300 0,-320 ; 60,-275 0,-255 ; 60,-235 0,-255 ; 60,-215 0,-195 ; 60,-175 0,-195 ; 60,-120 0,-100 ; 60,-80 0,-100 ; 60,2650 0,2670 ; 60,2690 0,2670 ; 60,3175 0,3195 ; 60,3215 0,3195 ; 149.08,2670 0,2670 ; 155,70 155,90 ; 205,60 225,0 ; 205,2350 225,2410 ; 215,0 235,0 ; 215,60 155,80 ; 215,100 155,80 ; 215,2410 235,2410 ; 225,929.08 225,0 ; 225,1480.92 225,2410 ; 245,60 225,0 ; 245,2350 225,2410 ; 255,80 155,80 ; 584.08,-195 0,-195 ; 650.92,2670 800,2670 ; 685,60 705,0 ; 685,2500 705,2560 ; 695,0 715,0 ; 695,2560 715,2560 ; 705,999.09 705,0 ; 705,1560.91 705,2560 ; 725,60 705,0 ; 725,2500 705,2560 ; 740,2650 800,2670 ; 740,2690 800,2670 ; 770,60 790,0 ; 770,1850 790,1910 ; 780,0 800,0 ; 780,1910 800,1910 ; 790,684.08 790,0 ; 790,1225.92 790,1910 ; 800,2660 800,2680 ; 810,60 790,0 ; 810,1850 790,1910 ; 1100,1910 1200,1910 ; 1125.92,-195 1710,-195 ; 1140,1890 1200,1910 ; 1140,1930 1200,1910 ; 1200,1900 1200,1920 ; 1344.09,-255 0,-255 ; 1400,1900 1400,1920 ; 1460,1890 1400,1910 ; 1460,1930 1400,1910 ; 1500,1910 1400,1910 ; 1650,-215 1710,-195 ; 1650,-175 1710,-195 ; 1710,-205 1710,-185 ; 1905.91,-255 3250,-255 ; 2114.09,-320 0,-320 ; 2519.09,3195 0,3195 ; 2675.91,-320 4790,-320 ; 2889.09,-400 0,-400 ; 2969.09,-100 0,-100 ; 3080.91,3195 5600,3195 ; 3190,-275 3250,-255 ; 3190,-235 3250,-255 ; 3250,-265 3250,-245 ; 3450.91,-400 6340,-400 ; 3530.91,-100 6500,-100 ; 4730,-340 4790,-320 ; 4730,-300 4790,-320 ; 4790,-330 4790,-310 ; 5540,3175 5600,3195 ; 5540,3215 5600,3195 ; 5600,3185 5600,3205 ; 6000,1395 6020,1455 ; 6000,1875 6020,1815 ; 6010,1455 6030,1455 ; 6010,1815 6030,1815 ; 6020,1355 6020,1455 ; 6020,1915 6020,1815 ; 6040,1395 6020,1455 ; 6040,1875 6020,1815 ; 6190,1465 6290,1465 ; 6230,1445 6290,1465 ; 6230,1485 6290,1465 ; 6280,-420 6340,-400 ; 6280,-380 6340,-400 ; 6290,1455 6290,1475 ; 6340,-410 6340,-390 ; 6440,-120 6500,-100 ; 6440,-80 6500,-100 ; 6500,-110 6500,-90 ; 6500,1455 6500,1475 ; 6560,1445 6500,1465 ; 6560,1485 6500,1465 ; 6600,1465 6500,1465 ; 6665,55 6685,-5 ; 6665,1380 6685,1440 ; 6675,-5 6695,-5 ; 6675,1440 6695,1440 ; 6685,441.58 6685,-5 ; 6685,993.42 6685,1440 ; 6705,55 6685,-5 ; 6705,1380 6685,1440
  text "5600 (mil)" at 2529.09,3159.01 h60
  text "800 (mil)" at 159.08,2634.01 h60
  text "4500 (mil)" at -94.01,1979.09 h60 r90
  text "200 (mil)" at 1059.08,1766.04 h60
  text "360 (mil)" at 6163.96,1394.08 h60 r90
  text "210 (mil)" at 6159.07,1321.04 h60
  text "2560 (mil)" at 740.99,1009.09 h60 r90
  text "2410 (mil)" at 260.99,939.08 h60 r90
  text "1910 (mil)" at 825.99,694.08 h60 r90
  text "1445 (mil)" at 6720.99,451.58 h60 r90
  text "160 (mil)" at -160.93,-63.96 h60
  text "6500 (mil)" at 2979.09,-135.99 h60
  text "160 (mil)" at -196.04,-140.93 h60 r90
  text "1710 (mil)" at 594.08,-230.99 h60
  text "3250 (mil)" at 1354.09,-290.99 h60
  text "4790 (mil)" at 2124.09,-355.99 h60
  text "6340 (mil)" at 2899.09,-435.99 h60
